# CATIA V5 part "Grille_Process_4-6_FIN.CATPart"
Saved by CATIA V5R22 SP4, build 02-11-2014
Part number: Grille
Bounding box of the stored display mesh (mm): x -173.245 to -100.001, y -313 to 313, z 227 to 413
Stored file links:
  C:\DATA\Car_ASSY\教育モデル\4_SUR\Grille_Process_4-6_FIN.CATPart
  C:\DATA\Car_ASSY\教育モデル\4_SUR\Grille_FIN.CATPart
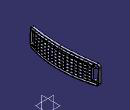
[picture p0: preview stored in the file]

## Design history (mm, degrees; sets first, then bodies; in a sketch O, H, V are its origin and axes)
Set1 "Danmen"
  Intersect1: ToIntersect1 Sweep1, ToIntersect2 Pad1
Set2 "Boss_Danmen"
  Sketch1 on Plane1, origin (-185, 0, 0), H (0, 1, 0), V (0, 0, 1)
    circle A1 centre (-280, 370) radius 6
    circle A2 centre (-280, 260) radius 6
    circle A3 centre (280, 370) radius 6
    circle A4 centre (280, 260) radius 6
    circle A5 centre (-280, 370) radius 9
    point P1 (-280, 370)
    circle A6 centre (-280, 260) radius 9
    point P2 (-280, 260)
    circle A7 centre (280, 260) radius 9
    point P3 (280, 260)
    circle A8 centre (280, 370) radius 9
    point P4 (280, 370)
    radius A5 = 9
    radius A6 = 9
    radius A7 = 9
    radius A8 = 9
    distance P4 V = 280
    distance H P4 = 370
    radius A3 = 6
    distance P3 P4 = 110
    distance V P3 = 280
    radius A4 = 6
    radius A2 = 6
    radius A1 = 6
    distance P1 V = 280
    distance P2 V = 280
    distance H P2 = 260
    distance P2 P1 = 110
    concentricity: P1 A1, P2 A2, P3 A4, P4 A3
  Plane1: type Offset, RefPlane yz-plane, Offset -185
Set3 "Front"
  Point1: (-1100, 0, 300)
  Circle1: type CtrRad, Start -30, End 30, Radius 1000, FirstDirection (1, 0, 0), Center Point1, Support xy-plane
  Circle2: type CtrRad, Start 165, End 195, Radius 1000, FirstDirection (-1, 0, 0), Center Point1, Support zx-plane
  Sweep1: type Unspec, Profile Circle2, Guide Circle1
Body1 (main body)
Body2
  Sketch2 on yz-plane, origin (0, 0, 0), H (0, 1, 0), V (0, 0, 1)
    point P1 (0.0002, 410)
    construction line L1 (0.0002, 410) -> (310, 410)
    point P2 (310, 410)
    line L2 (310, 372.6426) -> (310, 250)
    point P3 (310, 230)
    line L3 (290, 230) -> (0, 230)
    point P4 (0, 230)
    circle A1 centre (280, 370) radius 8
    circle A2 centre (280, 260) radius 8
    spline S1 through (0.0002, 410) (184.2802, 403.8794) (310, 390)
    arc A3 centre (290, 250) radius 20 from (290, 230) to (310, 250) ccw
    point P5 (290, 230)
    point P6 (310, 250)
    arc A4 centre (290, 372.6426) radius 20 from (292.7155, 392.4574) to (310, 372.6426) cw
    point P8 (292.7155, 392.4574)
    point P9 (310, 372.6426)
    offsetcurve C1
    point P11 (0.0002, 390)
    point P12 (290.0001, 372.6425)
    construction line L4 (0.0002, 410) -> (0.0002, 390)
    point P13 (0.0002, 410)
    construction line L5 through (0.0002, 410) direction (-1, 0)
    construction line L6 (292.7155, 392.4574) -> (290.0001, 372.6425)
    construction line L7 through (292.7155, 392.4574) direction (0.9907, -0.1358)
    line L8 (260, 376.4843) -> (260, 255)
    point P14 (257.373, 372.6426)
    point P15 (257.373, 250)
    construction line L9 (310, 372.6426) -> (257.373, 372.6426)
    construction line L10 (310, 250) -> (257.373, 250)
    line L11 (255, 250) -> (0, 250)
    point P16 (290, 250)
    point P17 (0, 250)
    construction line L12 (290, 230) -> (290, 250)
    construction line L13 (0, 230) -> (0, 250)
    point P18 (260, 376.4843)
    point P19 (260, 250)
    line L14 (272, 370) -> (260, 370)
    point P20 (272, 370)
    point P21 (260, 370)
    line L15 (288, 370) -> (310, 370)
    point P22 (288, 370)
    point P23 (310, 370)
    line L16 (288, 260) -> (310, 260)
    point P24 (288, 260)
    point P25 (310, 260)
    line L17 (272, 260) -> (260, 260)
    point P26 (272, 260)
    point P27 (260, 260)
    line L18 (260, 275) -> (0, 275)
    point P28 (260, 275)
    point P29 (0, 275)
    construction line L19 (260, 250) -> (260, 275)
    construction line L20 (0, 250) -> (0, 275)
    line L21 (260, 300) -> (0, 300)
    point P30 (260, 300)
    point P31 (0, 300)
    construction line L22 (260, 275) -> (260, 300)
    construction line L23 (0, 275) -> (0, 300)
    line L24 (260, 325) -> (0, 325)
    point P32 (260, 325)
    point P33 (0, 325)
    construction line L25 (260, 300) -> (260, 325)
    construction line L26 (0, 300) -> (0, 325)
    line L27 (260, 350) -> (0, 350)
    point P34 (260, 350)
    point P35 (0, 350)
    construction line L28 (260, 325) -> (260, 350)
    construction line L29 (0, 325) -> (0, 350)
    line L30 (260, 375) -> (0, 375)
    point P36 (260, 375)
    point P37 (0, 375)
    construction line L31 (260, 350) -> (260, 375)
    construction line L32 (0, 350) -> (0, 375)
    arc A5 centre (255, 255) radius 5 from (260, 255) to (255, 250) cw
    point P38 (260, 255)
    point P39 (255, 250)
    line L33 (17.5, 250) -> (17.5, 389.9532)
    point P41 (17.5, 250)
    point P42 (17.5, 389.9532)
    line L34 (52.5, 250) -> (52.5, 389.5709)
    point P43 (52.5, 250)
    point P44 (52.5, 389.5709)
    line L35 (87.5, 250) -> (87.5, 388.769)
    point P45 (87.5, 250)
    point P46 (87.5, 388.769)
    line L36 (122.5, 250) -> (122.5, 387.4859)
    point P47 (122.5, 250)
    point P48 (122.5, 387.4859)
    line L37 (157.5, 250) -> (157.5, 385.6484)
    point P49 (157.5, 250)
    point P50 (157.5, 385.6484)
    line L38 (192.5, 250) -> (192.5, 383.1854)
    point P51 (192.5, 250)
    point P52 (192.5, 383.1854)
    line L39 (227.5, 250) -> (227.5, 380.0419)
    point P53 (227.5, 250)
    point P54 (227.5, 380.0419)
    point P55 (-0.0002, 410)
    point P56 (-310, 410)
    construction line L40 (-0.0002, 410) -> (-310, 410)
    point P57 (-310, 230)
    point P58 (0, 230)
    point P59 (-290, 230)
    point P60 (-310, 250)
    point P62 (-292.7155, 392.4574)
    point P63 (-310, 372.6426)
    point P65 (-0.0002, 390)
    point P66 (-290.0001, 372.6425)
    point P67 (-257.373, 372.6426)
    point P68 (-257.373, 250)
    point P69 (-290, 250)
    point P70 (0, 250)
    point P71 (-260, 376.4843)
    point P72 (-260, 250)
    point P73 (-272, 370)
    point P74 (-260, 370)
    point P75 (-288, 370)
    point P76 (-310, 370)
    point P77 (-288, 260)
    point P78 (-310, 260)
    point P79 (-272, 260)
    point P80 (-260, 260)
    point P81 (-260, 275)
    point P82 (0, 275)
    point P83 (-260, 300)
    point P84 (0, 300)
    point P85 (-260, 325)
    point P86 (0, 325)
    point P87 (-260, 350)
    point P88 (0, 350)
    point P89 (-260, 375)
    point P90 (0, 375)
    point P91 (-260, 255)
    point P92 (-255, 250)
    point P94 (-17.5, 250)
    point P95 (-17.5, 389.9532)
    point P96 (-52.5, 250)
    point P97 (-52.5, 389.5709)
    point P98 (-87.5, 250)
    point P99 (-87.5, 388.769)
    point P100 (-122.5, 250)
    point P101 (-122.5, 387.4859)
    point P102 (-157.5, 250)
    point P103 (-157.5, 385.6484)
    point P104 (-192.5, 250)
    point P105 (-192.5, 383.1854)
    point P106 (-227.5, 250)
    point P107 (-227.5, 380.0419)
    line L41 (-310, 372.6426) -> (-310, 250)
    line L42 (-290, 230) -> (0, 230)
    circle A6 centre (-280, 370) radius 8
    circle A7 centre (-280, 260) radius 8
    spline S2 through (-0.0002, 410) (-184.2802, 403.8794) (-310, 390)
    arc A8 centre (-290, 250) radius 20 from (-290, 230) to (-310, 250) cw
    arc A9 centre (-290, 372.6426) radius 20 from (-292.7155, 392.4574) to (-310, 372.6426) ccw
    offsetcurve C2
    line L43 (-260, 376.4843) -> (-260, 255)
    line L44 (-255, 250) -> (0, 250)
    line L45 (-272, 370) -> (-260, 370)
    line L46 (-288, 370) -> (-310, 370)
    line L47 (-288, 260) -> (-310, 260)
    line L48 (-272, 260) -> (-260, 260)
    line L49 (-260, 275) -> (0, 275)
    line L50 (-260, 300) -> (0, 300)
    line L51 (-260, 325) -> (0, 325)
    line L52 (-260, 350) -> (0, 350)
    line L53 (-260, 375) -> (0, 375)
    arc A10 centre (-255, 255) radius 5 from (-260, 255) to (-255, 250) ccw
    line L54 (-17.5, 250) -> (-17.5, 389.9532)
    line L55 (-52.5, 250) -> (-52.5, 389.5709)
    line L56 (-87.5, 250) -> (-87.5, 388.769)
    line L57 (-122.5, 250) -> (-122.5, 387.4859)
    line L58 (-157.5, 250) -> (-157.5, 385.6484)
    line L59 (-192.5, 250) -> (-192.5, 383.1854)
    line L60 (-227.5, 250) -> (-227.5, 380.0419)
    point P108 (0.0002, 410)
    point P109 (310, 390)
    point P110 (184.2802, 403.8794)
    point P111 (-0.0002, 410)
    point P112 (-310, 390)
    point P113 (-184.2802, 403.8794)
    distance H L3 = 230
    distance L2 V = 310
    distance P109 L1 = 20
    distance P2 P3 = 180
    distance V P110 = 184.2802
    distance P110 P109 V = 13.8794
    distance P108 P4 = 180
    radius A3 = 20
    radius A4 = 20
    distance L2 L8 = 50
    distance L3 L11 = 20
    distance L16 L3 = 30
    distance L15 L16 = 110
    distance A1 L15 = 8
    distance A1 L15 = 8
    distance A1 L2 = 38
    distance A2 L16 = 8
    distance A2 L16 = 8
    distance L2 A2 = 38
    distance L11 L18 = 25
    distance L18 L21 = 25
    distance L21 L24 = 25
    distance L24 L27 = 25
    distance L27 L30 = 25
    radius A5 = 5
    distance V L33 = 17.5
    distance L33 L34 = 35
    distance L34 L35 = 35
    distance L35 L36 = 35
    distance L36 L37 = 35
    distance L37 L38 = 35
    distance L38 L39 = 35
    horizontal: L1 H, L3 H, L14 H, L15 H, L16 H, L17 H
    vertical: L2 V, L33 V, L34 V, L35 V, L36 V, L37 V, L38 V, L39 V
    coincidence: P4 V, P108 P1, P109 L2, P2 L2, L3 P3, L2 P3, P108 P13, P12 C1, P16 L11, P20 A1, P21 L8, P22 L14, P22 A1, P23 L2, P24 A2, P25 L2, P26 L16, P26 A2, P27 L8, L8 P19, L11 P19, P41 L11, P42 C1, P43 L11, P44 C1, P45 L11, P46 C1, P47 L11, P48 C1, P49 L11, P50 C1, P51 L11, P52 C1, P53 L11, P54 C1, P4 P58, P17 P70, P29 P82, P31 P84, P33 P86, P35 P88, P37 P90
    tangency: A3 L3, A3 L2, A4 S1, A4 L2, L5 S1, L7 S1, A5 L8, A5 L11
    perpendicularity: L4 L5, L6 L7, L9 L2, L9 L8, L10 L2, L10 L8, L12 L3, L12 L11, L13 L3, L13 L11, L19 L11, L19 L18, L20 L11, L20 L18, L22 L18, L22 L21, L23 L18, L23 L21, L25 L21, L25 L24, L26 L21, L26 L24, L28 L24, L28 L27, L29 L24, L29 L27, L31 L27, L31 L30, L32 L27, L32 L30
    symmetry: P1 P55 V, P2 P56 V, L1 L40 V, P3 P57 V, P4 P58 V, P5 P59 V, P6 P60 V, P8 P62 V, P9 P63 V, P11 P65 V, P12 P66 V, P14 P67 V, P15 P68 V, P16 P69 V, P17 P70 V, P18 P71 V, P19 P72 V, P20 P73 V, P21 P74 V, P22 P75 V, P23 P76 V, P24 P77 V, P25 P78 V, P26 P79 V, P27 P80 V, P28 P81 V, P29 P82 V, P30 P83 V, P31 P84 V, P32 P85 V, P33 P86 V, P34 P87 V, P35 P88 V, P36 P89 V, P37 P90 V, P38 P91 V, P39 P92 V, P41 P94 V, P42 P95 V, P43 P96 V, P44 P97 V, P45 P98 V, P46 P99 V, P47 P100 V, P48 P101 V, P49 P102 V, P50 P103 V, P51 P104 V, P52 P105 V, P53 P106 V, P54 P107 V, L2 L41 V, L3 L42 V, A1 A6 V, A2 A7 V, S1 S2 V, A3 A8 V, A4 A9 V, C1 C2 V, L8 L43 V, L11 L44 V, L14 L45 V, L15 L46 V, L16 L47 V, L17 L48 V, L18 L49 V, L21 L50 V, L24 L51 V, L27 L52 V, L30 L53 V, A5 A10 V, L33 L54 V, L34 L55 V, L35 L56 V, L36 L57 V, L37 L58 V, L38 L59 V, L39 L60 V, P108 P111 V, P109 P112 V, P110 P113 V
  Pad1: profile Sketch2, direction (-1, 0, 0), length 350, thin wall 6
Body3
  Pad2: profile Intersect1, direction along X axis reversed, length 20
  Fillet1: radius 2, on face of Pad2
